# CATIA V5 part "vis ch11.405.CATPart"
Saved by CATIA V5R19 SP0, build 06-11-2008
Part number: vis ch11.406
Bounding box of the stored display mesh (mm): x 0 to 7.4, y -1.3 to 1.3, z -1.3 to 1.3
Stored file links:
  I:\mediator\vis ch11.405.CATPart
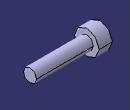
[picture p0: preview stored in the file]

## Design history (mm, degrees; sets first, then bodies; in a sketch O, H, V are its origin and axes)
Body1 (main body)
  Sketch1 on yz-plane, origin (0, 0, 0), H (0, 1, 0), V (0, 0, 1)
    circle A1 centre (0, 0) radius 1.3
    radius A1 = 1.3
  Pad1: profile Sketch1, direction (1, 0, 0), length 1.4
  Sketch2 on end face of Pad1, origin (1.4, 0, 0), H (0, 1, 0), V (0, 0, 1)
    circle A1 centre (0, 0) radius 0.7
    radius A1 = 0.7
  Pad2: profile Sketch2, direction (1, 0, 0), length 6
  Sketch3 on start face of Pad1, origin (0, 0, 0), H (0, -1, 0), V (0, 0, 1)
    point P1 (0.5914, -0.2697)
    line L1 (0.5914, -0.2697) -> (0.5914, 0.2697)
    point P2 (0.5914, 0.2697)
    line L2 (0.5914, 0.2697) -> (0, 0.65)
    point P3 (0, 0.65)
    line L3 (0.5914, -0.2697) -> (0, -0.65)
    point P4 (0, -0.65)
    axis line L4 (0, 0.8043) -> (0, -0.9585)
    point P5 (0, 0.8043)
    point P7 (0, -0.65)
    point P8 (-0.5914, -0.2697)
    line L5 (-0.5914, -0.2697) -> (0, -0.65)
    point P9 (-0.5914, 0.2697)
    line L6 (-0.5914, -0.2697) -> (-0.5914, 0.2697)
    point P10 (0, 0.65)
    line L7 (-0.5914, 0.2697) -> (0, 0.65)
    vertical: L1 V, L4 V
    coincidence: P3 V, P4 V, P5 V, P3 P10, P4 P7
    symmetry: P4 P7 L4, P1 P8 L4, L3 L5 L4, P2 P9 L4, L1 L6 L4, P3 P10 L4, L2 L7 L4
  Pocket1: profile Sketch3, direction (1, 0, 0), length 1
